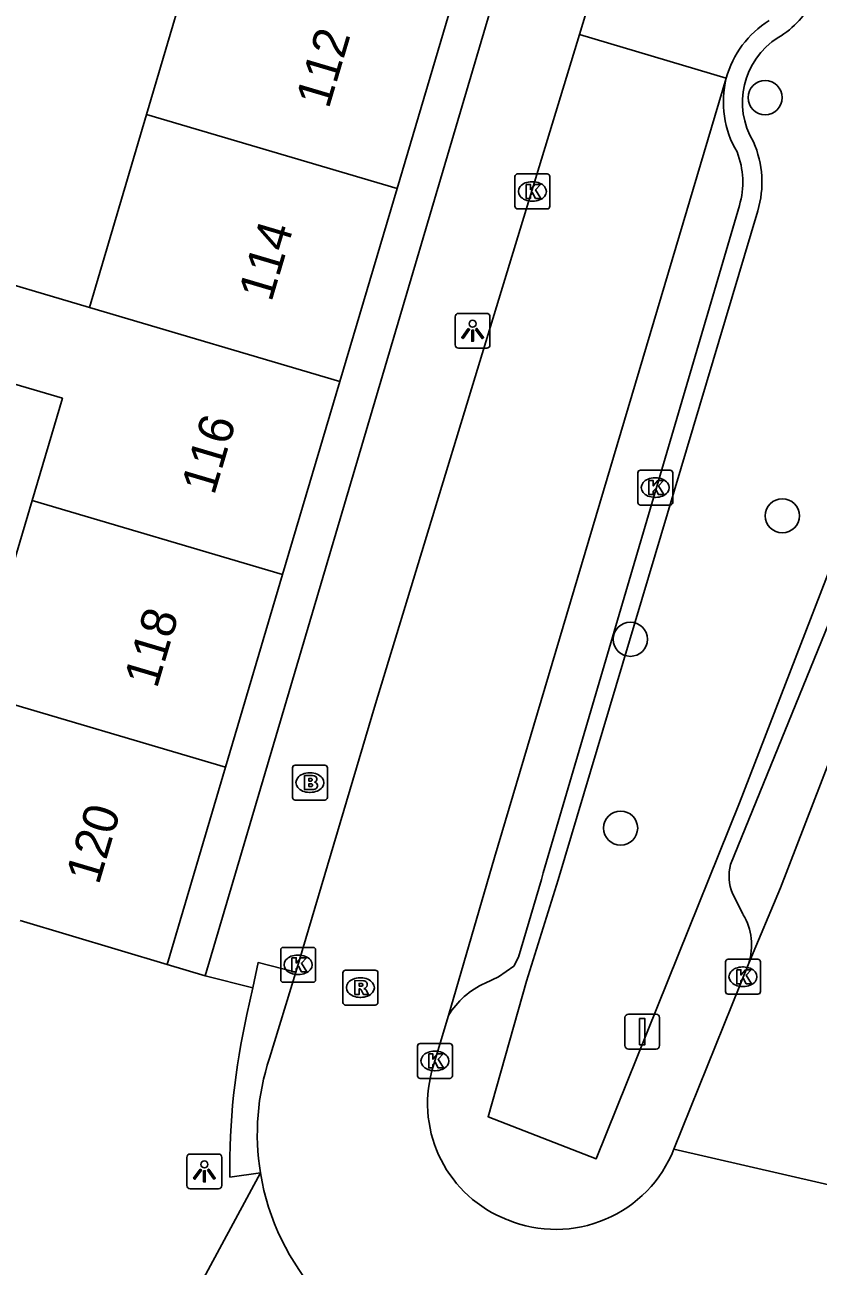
# Model space of a CAD drawing. Extents: x 160356 to 161355, y 381727 to 382845.
# Drawn here: x 160605.96 to 160628.69, y 382020.52 to 382056.09 of the extents above; entities that cross this region are included whole.
import ezdxf

# ---------------------------------------------------------------- set-up
doc = ezdxf.new("R2010")
doc.units = 0
for name, color, linetype in [('IMGEO_Boom', 7, 'Continuous'), ('IMGEO_Brandkraan', 7, 'Continuous'), ('IMGEO_Kolk', 7, 'Continuous'), ('IMGEO_Lichtpunt', 7, 'Continuous'), ('IMGEO_Pand', 7, 'Continuous'), ('IMGEO_Pand_nummerreeks', 7, 'Continuous'), ('IMGEO_Rijbaan_lokaal_open', 7, 'Continuous'), ('IMGEO_Rioolput', 7, 'Continuous'), ('IMGEO_Verkeersbordpaal', 7, 'Continuous'), ('IMGEO_Voetpad_open', 7, 'Continuous')]:
    doc.layers.add(name, color=color, linetype=linetype)

msp = doc.modelspace()

# ---------------------------------------------------------------- linework, layer by layer
at = {"layer": 'IMGEO_Boom'}
for centre in [(160627.173, 382054.001), (160627.665, 382042.02), (160623.311, 382038.482), (160623.032, 382033.072)]:
    msp.add_circle(centre, 0.489, dxfattribs=at)
at = {"layer": 'IMGEO_Brandkraan'}
for p, q in [((160613.631, 382033.949), (160613.631, 382034.801)), ((160613.706, 382034.875), (160614.558, 382034.875)), ((160614.119, 382034.655), (160614.144, 382034.655)), ((160614.632, 382034.801), (160614.632, 382033.949)), ((160614.558, 382033.875), (160613.706, 382033.875)), ((160614.142, 382034.095), (160614.117, 382034.095))]:
    msp.add_line(p, q, dxfattribs=at)
for points in [[(160613.631, 382033.949), (160613.631, 382034.801)], [(160613.706, 382034.875), (160614.558, 382034.875)], [(160613.979, 382034.575), (160613.979, 382034.175), (160614.192, 382034.175)], [(160614.21, 382034.575), (160613.979, 382034.575)], [(160614.632, 382034.801), (160614.632, 382033.949)], [(160614.158, 382034.494), (160614.104, 382034.494), (160614.104, 382034.418)], [(160614.104, 382034.418), (160614.157, 382034.418)], [(160614.166, 382034.342), (160614.104, 382034.342), (160614.104, 382034.261)], [(160614.104, 382034.261), (160614.166, 382034.261)], [(160614.558, 382033.875), (160613.706, 382033.875)]]:
    msp.add_lwpolyline(points, dxfattribs=at)
for centre, radius, start, end in [((160613.708, 382034.799), 0.0765, 91.552, 178.448), ((160613.708, 382034.799), 0.0765, 91.552, 178.448), ((160614.214, 382034.43), 0.145, 59.4692, 91.5367), ((160614.239, 382034.477), 0.0922, 285.5137, 58.1501), ((160614.556, 382034.799), 0.0765, 1.552, 88.448), ((160614.556, 382034.799), 0.0765, 1.552, 88.448), ((160614.159, 382034.456), 0.0379, 267.8285, 90.9355), ((160614.167, 382034.301), 0.0404, 269.8759, 90.5077), ((160614.198, 382034.426), 0.251, 268.6676, 293.5347), ((160614.244, 382034.285), 0.105, 301.3115, 78.989), ((160613.708, 382033.951), 0.0765, 181.552, 268.448), ((160613.708, 382033.951), 0.0765, 181.552, 268.448), ((160614.556, 382033.951), 0.0765, 271.552, 358.448), ((160614.556, 382033.951), 0.0765, 271.552, 358.448)]:
    msp.add_arc(centre, radius, start, end, dxfattribs=at)
for centre, major_axis, ratio, start_param, end_param in [((160614.118, 382034.375), (-0.387, 0.002), 0.722429, 4.712389, 7.853982), ((160614.143, 382034.375), (-0.39, 0.002), 0.717154, 1.570796, 4.712389)]:
    msp.add_ellipse(centre, major_axis=major_axis, ratio=ratio, start_param=start_param, end_param=end_param, dxfattribs=at)
at = {"layer": 'IMGEO_Kolk'}
for p, q in [((160620.004, 382050.887), (160620.004, 382051.739)), ((160620.079, 382051.813), (160620.931, 382051.813)), ((160621.005, 382051.739), (160621.005, 382050.887)), ((160620.492, 382051.593), (160620.517, 382051.593)), ((160620.515, 382051.033), (160620.49, 382051.033)), ((160620.931, 382050.813), (160620.079, 382050.813)), ((160623.524, 382042.402), (160623.524, 382043.254)), ((160623.599, 382043.328), (160624.451, 382043.328)), ((160624.012, 382043.108), (160624.037, 382043.108)), ((160624.525, 382043.254), (160624.525, 382042.402)), ((160624.035, 382042.548), (160624.01, 382042.548)), ((160624.451, 382042.328), (160623.599, 382042.328)), ((160613.294, 382028.729), (160613.294, 382029.581)), ((160613.369, 382029.655), (160614.221, 382029.655)), ((160614.295, 382029.581), (160614.295, 382028.729)), ((160613.782, 382029.435), (160613.807, 382029.435)), ((160626.037, 382028.387), (160626.037, 382029.239)), ((160626.112, 382029.313), (160626.964, 382029.313)), ((160627.038, 382029.239), (160627.038, 382028.387)), ((160613.805, 382028.875), (160613.78, 382028.875)), ((160626.525, 382029.093), (160626.55, 382029.093)), ((160614.221, 382028.655), (160613.369, 382028.655)), ((160626.548, 382028.533), (160626.523, 382028.533)), ((160626.964, 382028.313), (160626.112, 382028.313)), ((160617.213, 382025.975), (160617.213, 382026.827)), ((160617.288, 382026.901), (160618.14, 382026.901)), ((160618.214, 382026.827), (160618.214, 382025.975)), ((160617.701, 382026.681), (160617.726, 382026.681)), ((160617.724, 382026.121), (160617.699, 382026.121)), ((160618.14, 382025.901), (160617.288, 382025.901))]:
    msp.add_line(p, q, dxfattribs=at)
for points in [[(160620.004, 382050.887), (160620.004, 382051.739)], [(160620.079, 382051.813), (160620.931, 382051.813)], [(160621.005, 382051.739), (160621.005, 382050.887)], [(160620.325, 382051.513), (160620.448, 382051.513), (160620.448, 382051.362), (160620.578, 382051.513), (160620.742, 382051.513), (160620.596, 382051.362), (160620.749, 382051.113), (160620.597, 382051.113), (160620.512, 382051.277), (160620.448, 382051.21), (160620.448, 382051.113), (160620.325, 382051.113), (160620.325, 382051.513)], [(160620.931, 382050.813), (160620.079, 382050.813)], [(160623.524, 382042.402), (160623.524, 382043.254)], [(160623.599, 382043.328), (160624.451, 382043.328)], [(160624.525, 382043.254), (160624.525, 382042.402)], [(160623.845, 382043.028), (160623.968, 382043.028), (160623.968, 382042.877), (160624.098, 382043.028), (160624.262, 382043.028), (160624.116, 382042.877), (160624.269, 382042.628), (160624.117, 382042.628), (160624.032, 382042.792), (160623.968, 382042.725), (160623.968, 382042.628), (160623.845, 382042.628), (160623.845, 382043.028)], [(160624.451, 382042.328), (160623.599, 382042.328)], [(160613.294, 382028.729), (160613.294, 382029.581)], [(160613.369, 382029.655), (160614.221, 382029.655)], [(160614.295, 382029.581), (160614.295, 382028.729)], [(160613.615, 382029.355), (160613.738, 382029.355), (160613.738, 382029.204), (160613.868, 382029.355), (160614.032, 382029.355), (160613.886, 382029.204), (160614.039, 382028.955), (160613.887, 382028.955), (160613.802, 382029.119), (160613.738, 382029.052), (160613.738, 382028.955), (160613.615, 382028.955), (160613.615, 382029.355)], [(160626.037, 382028.387), (160626.037, 382029.239)], [(160626.112, 382029.313), (160626.964, 382029.313)], [(160627.038, 382029.239), (160627.038, 382028.387)], [(160626.358, 382029.013), (160626.481, 382029.013), (160626.481, 382028.862), (160626.611, 382029.013), (160626.775, 382029.013), (160626.629, 382028.862), (160626.782, 382028.613), (160626.63, 382028.613), (160626.545, 382028.777), (160626.481, 382028.71), (160626.481, 382028.613), (160626.358, 382028.613), (160626.358, 382029.013)], [(160614.221, 382028.655), (160613.369, 382028.655)], [(160626.964, 382028.313), (160626.112, 382028.313)], [(160617.213, 382025.975), (160617.213, 382026.827)], [(160617.288, 382026.901), (160618.14, 382026.901)], [(160618.214, 382026.827), (160618.214, 382025.975)], [(160617.534, 382026.601), (160617.657, 382026.601), (160617.657, 382026.45), (160617.787, 382026.601), (160617.951, 382026.601), (160617.805, 382026.45), (160617.958, 382026.201), (160617.806, 382026.201), (160617.721, 382026.365), (160617.657, 382026.298), (160617.657, 382026.201), (160617.534, 382026.201), (160617.534, 382026.601)], [(160618.14, 382025.901), (160617.288, 382025.901)]]:
    msp.add_lwpolyline(points, dxfattribs=at)
for centre, start, end in [((160620.081, 382051.737), 91.552, 178.448), ((160620.081, 382051.737), 91.552, 178.448), ((160620.929, 382051.737), 1.552, 88.448), ((160620.929, 382051.737), 1.552, 88.448), ((160620.081, 382050.889), 181.552, 268.448), ((160620.081, 382050.889), 181.552, 268.448), ((160620.929, 382050.889), 271.552, 358.448), ((160620.929, 382050.889), 271.552, 358.448), ((160623.601, 382043.252), 91.552, 178.448), ((160623.601, 382043.252), 91.552, 178.448), ((160624.449, 382043.252), 1.552, 88.448), ((160624.449, 382043.252), 1.552, 88.448), ((160623.601, 382042.404), 181.552, 268.448), ((160623.601, 382042.404), 181.552, 268.448), ((160624.449, 382042.404), 271.552, 358.448), ((160624.449, 382042.404), 271.552, 358.448), ((160613.371, 382029.579), 91.552, 178.448), ((160613.371, 382029.579), 91.552, 178.448), ((160614.219, 382029.579), 1.552, 88.448), ((160614.219, 382029.579), 1.552, 88.448), ((160626.114, 382029.237), 91.552, 178.448), ((160626.114, 382029.237), 91.552, 178.448), ((160626.962, 382029.237), 1.552, 88.448), ((160626.962, 382029.237), 1.552, 88.448), ((160613.371, 382028.731), 181.552, 268.448), ((160613.371, 382028.731), 181.552, 268.448), ((160614.219, 382028.731), 271.552, 358.448), ((160614.219, 382028.731), 271.552, 358.448), ((160626.114, 382028.389), 181.552, 268.448), ((160626.114, 382028.389), 181.552, 268.448), ((160626.962, 382028.389), 271.552, 358.448), ((160626.962, 382028.389), 271.552, 358.448), ((160617.29, 382026.825), 91.552, 178.448), ((160617.29, 382026.825), 91.552, 178.448), ((160618.138, 382026.825), 1.552, 88.448), ((160618.138, 382026.825), 1.552, 88.448), ((160617.29, 382025.977), 181.552, 268.448), ((160617.29, 382025.977), 181.552, 268.448), ((160618.138, 382025.977), 271.552, 358.448), ((160618.138, 382025.977), 271.552, 358.448)]:
    msp.add_arc(centre, 0.0765, start, end, dxfattribs=at)
for centre, major_axis, ratio, start_param, end_param in [((160620.491, 382051.313), (-0.387, 0.002), 0.722429, 4.712389, 7.853982), ((160620.516, 382051.313), (-0.39, 0.002), 0.717154, 1.570796, 4.712389), ((160624.011, 382042.828), (-0.387, 0.002), 0.722429, 4.712389, 7.853982), ((160624.036, 382042.828), (-0.39, 0.002), 0.717154, 1.570796, 4.712389), ((160613.781, 382029.155), (-0.387, 0.002), 0.722429, 4.712389, 7.853982), ((160613.806, 382029.155), (-0.39, 0.002), 0.717154, 1.570796, 4.712389), ((160626.524, 382028.813), (-0.387, 0.002), 0.722429, 4.712389, 7.853982), ((160626.549, 382028.813), (-0.39, 0.002), 0.717154, 1.570796, 4.712389), ((160617.7, 382026.401), (-0.387, 0.002), 0.722429, 4.712389, 7.853982), ((160617.725, 382026.401), (-0.39, 0.002), 0.717154, 1.570796, 4.712389)]:
    msp.add_ellipse(centre, major_axis=major_axis, ratio=ratio, start_param=start_param, end_param=end_param, dxfattribs=at)
at = {"layer": 'IMGEO_Lichtpunt'}
for p, q in [((160618.294, 382047.725), (160618.294, 382046.918)), ((160618.294, 382047.725), (160618.294, 382046.918)), ((160619.196, 382047.82), (160618.388, 382047.82)), ((160619.196, 382047.82), (160618.388, 382047.82)), ((160619.29, 382046.918), (160619.29, 382047.725)), ((160619.29, 382046.918), (160619.29, 382047.725)), ((160618.388, 382046.824), (160619.196, 382046.824)), ((160618.388, 382046.824), (160619.196, 382046.824)), ((160610.61, 382023.639), (160610.61, 382022.832)), ((160610.61, 382023.639), (160610.61, 382022.832)), ((160611.512, 382023.734), (160610.704, 382023.734)), ((160611.512, 382023.734), (160610.704, 382023.734)), ((160611.606, 382022.832), (160611.606, 382023.639)), ((160611.606, 382022.832), (160611.606, 382023.639)), ((160610.704, 382022.738), (160611.512, 382022.738)), ((160610.704, 382022.738), (160611.512, 382022.738))]:
    msp.add_line(p, q, dxfattribs=at)
for points in [[(160618.668, 382047.389), (160618.707, 382047.361), (160618.519, 382047.099), (160618.481, 382047.126), (160618.668, 382047.389)], [(160618.88, 382047.361), (160618.918, 382047.388), (160619.105, 382047.126), (160619.066, 382047.098), (160618.88, 382047.361)], [(160618.77, 382047.341), (160618.817, 382047.341), (160618.817, 382047.019), (160618.77, 382047.019), (160618.77, 382047.341)], [(160610.984, 382023.303), (160611.023, 382023.275), (160610.835, 382023.013), (160610.797, 382023.04), (160610.984, 382023.303)], [(160611.086, 382023.255), (160611.133, 382023.255), (160611.133, 382022.933), (160611.086, 382022.933), (160611.086, 382023.255)], [(160611.196, 382023.275), (160611.234, 382023.302), (160611.421, 382023.04), (160611.382, 382023.012), (160611.196, 382023.275)]]:
    msp.add_lwpolyline(points, dxfattribs=at)
for centre in [(160618.793, 382047.523), (160611.109, 382023.437)]:
    msp.add_circle(centre, 0.0994, dxfattribs=at)
for centre, start, end in [((160618.388, 382047.725), 90, 180), ((160618.388, 382047.725), 90, 180), ((160619.196, 382047.725), 0, 90), ((160619.196, 382047.725), 0, 90), ((160618.388, 382046.918), 180, 270), ((160618.388, 382046.918), 180, 270), ((160619.196, 382046.918), 270, 0), ((160619.196, 382046.918), 270, 360), ((160610.704, 382023.639), 90, 180), ((160610.704, 382023.639), 90, 180), ((160611.512, 382023.639), 0, 90), ((160611.512, 382023.639), 0, 90), ((160610.704, 382022.832), 180, 270), ((160610.704, 382022.832), 180, 270), ((160611.512, 382022.832), 270, 0), ((160611.512, 382022.832), 270, 360)]:
    msp.add_arc(centre, 0.0946, start, end, dxfattribs=at)
at = {"layer": 'IMGEO_Pand'}
for points in [[(160609.451, 382053.517), (160611.088, 382059.043)], [(160616.627, 382051.396), (160618.264, 382056.922)], [(160607.813, 382047.99), (160609.451, 382053.517)], [(160609.451, 382053.517), (160616.627, 382051.396)], [(160614.989, 382045.87), (160616.627, 382051.396)], [(160607.813, 382047.99), (160604.262, 382049.039), (160603.492, 382046.434), (160607.041, 382045.386), (160606.175, 382042.463)], [(160614.989, 382045.87), (160607.813, 382047.99)], [(160613.351, 382040.342), (160614.989, 382045.87)], [(160606.175, 382042.463), (160604.537, 382036.937)], [(160606.175, 382042.463), (160613.351, 382040.342)], [(160611.714, 382034.817), (160613.351, 382040.342)], [(160604.537, 382036.937), (160611.714, 382034.817)], [(160610.04, 382029.166), (160611.714, 382034.817)], [(160610.04, 382029.166), (160605.827, 382030.426)]]:
    msp.add_lwpolyline(points, dxfattribs=at)
at = {"layer": 'IMGEO_Rijbaan_lokaal_open'}
for points in [[(160621.857, 382055.808), (160622.269, 382057.18)], [(160613.73, 382028.944), (160616.013, 382036.634), (160621.857, 382055.808)], [(160626.06, 382054.558), (160621.857, 382055.808)], [(160618.099, 382027.706), (160619.417, 382032.232), (160626.06, 382054.558)], [(160633.552, 382046.584), (160630.632, 382039.179), (160627.611, 382031.358), (160626.701, 382029.199)], [(160612.973, 382026.477), (160613.73, 382028.944)], [(160624.558, 382023.872), (160626.701, 382029.199)], [(160618.099, 382027.706), (160617.629, 382026.115)], [(160629.825, 382022.664), (160624.558, 382023.872)]]:
    msp.add_lwpolyline(points, dxfattribs=at)
for centre, radius, start, end in [((160628.773, 382053.821), 2.812, 121.8663, 164.8059), ((160619.575, 382024.304), 6.95, 161.7793, 189.2046), ((160621.066, 382025.177), 3.563, 164.7396, 249.1293), ((160621.177, 382025.21), 3.637, 293.0612, 338.4126), ((160619.555, 382024.303), 6.93, 189.226, 255.0594), ((160621.18, 382025.201), 3.627, 247.5858, 293.0681)]:
    msp.add_arc(centre, radius, start, end, dxfattribs=at)
at = {"layer": 'IMGEO_Rioolput'}
for p, q in [((160615.078, 382028.076), (160615.078, 382028.928)), ((160615.153, 382029.002), (160616.005, 382029.002)), ((160616.079, 382028.928), (160616.079, 382028.076)), ((160615.566, 382028.782), (160615.591, 382028.782)), ((160615.589, 382028.222), (160615.564, 382028.222)), ((160616.005, 382028.002), (160615.153, 382028.002))]:
    msp.add_line(p, q, dxfattribs=at)
for points in [[(160615.078, 382028.076), (160615.078, 382028.928)], [(160615.153, 382029.002), (160616.005, 382029.002)], [(160616.079, 382028.928), (160616.079, 382028.076)], [(160615.667, 382028.7), (160615.415, 382028.702), (160615.415, 382028.302)], [(160615.593, 382028.621), (160615.539, 382028.621), (160615.539, 382028.54)], [(160615.539, 382028.54), (160615.591, 382028.54)], [(160615.415, 382028.302), (160615.539, 382028.302), (160615.539, 382028.464), (160615.55, 382028.464)], [(160615.597, 382028.435), (160615.668, 382028.302), (160615.808, 382028.302), (160615.743, 382028.428)], [(160616.005, 382028.002), (160615.153, 382028.002)]]:
    msp.add_lwpolyline(points, dxfattribs=at)
for centre, radius, start, end in [((160615.155, 382028.926), 0.0765, 91.552, 178.448), ((160615.155, 382028.926), 0.0765, 91.552, 178.448), ((160616.003, 382028.926), 0.0765, 1.552, 88.448), ((160616.003, 382028.926), 0.0765, 1.552, 88.448), ((160615.575, 382028.729), 0.19, 274.7715, 282.9687), ((160615.599, 382028.525), 0.0964, 77.0061, 93.1865), ((160615.613, 382028.582), 0.0378, 276.6634, 79.6772), ((160615.666, 382028.59), 0.109, 350.3612, 89.416), ((160615.664, 382028.59), 0.112, 277.5842, 350.9817), ((160615.549, 382028.411), 0.0533, 26.0293, 88.6989), ((160615.648, 382028.375), 0.108, 29.5134, 73.7905), ((160615.155, 382028.078), 0.0765, 181.552, 268.448), ((160615.155, 382028.078), 0.0765, 181.552, 268.448), ((160616.003, 382028.078), 0.0765, 271.552, 358.448), ((160616.003, 382028.078), 0.0765, 271.552, 358.448)]:
    msp.add_arc(centre, radius, start, end, dxfattribs=at)
for centre, major_axis, ratio, start_param, end_param in [((160615.565, 382028.502), (-0.387, 0.002), 0.722429, 4.712389, 7.853982), ((160615.59, 382028.502), (-0.39, 0.002), 0.717154, 1.570796, 4.712389)]:
    msp.add_ellipse(centre, major_axis=major_axis, ratio=ratio, start_param=start_param, end_param=end_param, dxfattribs=at)
at = {"layer": 'IMGEO_Verkeersbordpaal'}
for p, q in [((160623.158, 382026.841), (160623.158, 382027.641)), ((160623.158, 382027.641), (160623.158, 382026.841)), ((160623.258, 382027.741), (160624.048, 382027.741)), ((160624.048, 382027.741), (160623.258, 382027.741)), ((160624.148, 382027.641), (160624.148, 382026.841)), ((160624.148, 382026.841), (160624.148, 382027.641)), ((160624.048, 382026.741), (160623.258, 382026.741)), ((160623.258, 382026.741), (160624.048, 382026.741))]:
    msp.add_line(p, q, dxfattribs=at)
msp.add_lwpolyline([(160623.578, 382027.616), (160623.728, 382027.616), (160623.728, 382026.866), (160623.578, 382026.866), (160623.578, 382027.616)], dxfattribs=at)
for centre, start, end in [((160623.258, 382027.641), 90, 180), ((160623.258, 382027.641), 90, 180), ((160624.048, 382027.641), 0, 90), ((160624.048, 382027.641), 360, 90), ((160623.258, 382026.841), 180, 270), ((160623.258, 382026.841), 180, 270), ((160624.048, 382026.841), 270, 0), ((160624.048, 382026.841), 270, 0)]:
    msp.add_arc(centre, 0.1, start, end, dxfattribs=at)
at = {"layer": 'IMGEO_Voetpad_open'}
for points in [[(160630.764, 382095.322), (160611.134, 382028.835)], [(160626.435, 382050.912), (160620.812, 382031.788), (160620.764, 382031.596), (160620.11, 382029.377), (160619.975, 382029.117), (160619.538, 382028.811), (160619.149, 382028.631)], [(160626.962, 382050.755), (160621.244, 382031.591), (160620.334, 382028.69), (160619.235, 382024.803), (160622.332, 382023.593), (160626.437, 382033.795), (160630.67, 382044.739)], [(160626.181, 382032.029), (160629.308, 382039.719), (160631.266, 382044.554)], [(160626.543, 382030.592), (160626.241, 382031.202)], [(160612.492, 382028.495), (160612.647, 382029.219), (160613.73, 382028.944)], [(160611.134, 382028.835), (160610.04, 382029.166)], [(160612.492, 382028.495), (160611.134, 382028.835)], [(160612.329, 382027.732), (160612.492, 382028.495)], [(160610.821, 382019.688), (160612.714, 382023.192)], [(160612.714, 382023.192), (160611.839, 382023.072)]]:
    msp.add_lwpolyline(points, dxfattribs=at)
for centre, radius, start, end in [((160626.202, 382057.977), 2.625, 300.8527, 334.851), ((160628.706, 382053.869), 2.185, 121.9852, 211.3886), ((160628.78, 382053.875), 2.804, 165.9129, 210.6737), ((160624.183, 382051.575), 2.897, 343.555, 23.511), ((160624.18, 382051.581), 2.353, 343.4695, 21.5355), ((160627.397, 382031.702), 1.259, 164.9248, 203.3745), ((160625.103, 382029.723), 1.682, 341.8448, 31.0974), ((160620.159, 382026.426), 2.426, 114.6129, 148.1441), ((160631.537, 382023.356), 19.7, 167.1674, 180.8274)]:
    msp.add_arc(centre, radius, start, end, dxfattribs=at)

# ---------------------------------------------------------------- texts
at = {"layer": 'IMGEO_Pand_nummerreeks'}
for s, rotation, p in [('112', 73.4957, (160614.668, 382053.656)), ('114', 73.4957, (160613.028, 382048.121)), ('116', 73.4933, (160611.387, 382042.584)), ('118', 73.4933, (160609.747, 382037.047)), ('120', 73.4933, (160608.08, 382031.421))]:
    msp.add_text(s, height=1, rotation=rotation, dxfattribs=at).set_placement(p)

doc.saveas('drawing.dxf')
